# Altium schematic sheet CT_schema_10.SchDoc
size 318 x 188 mm
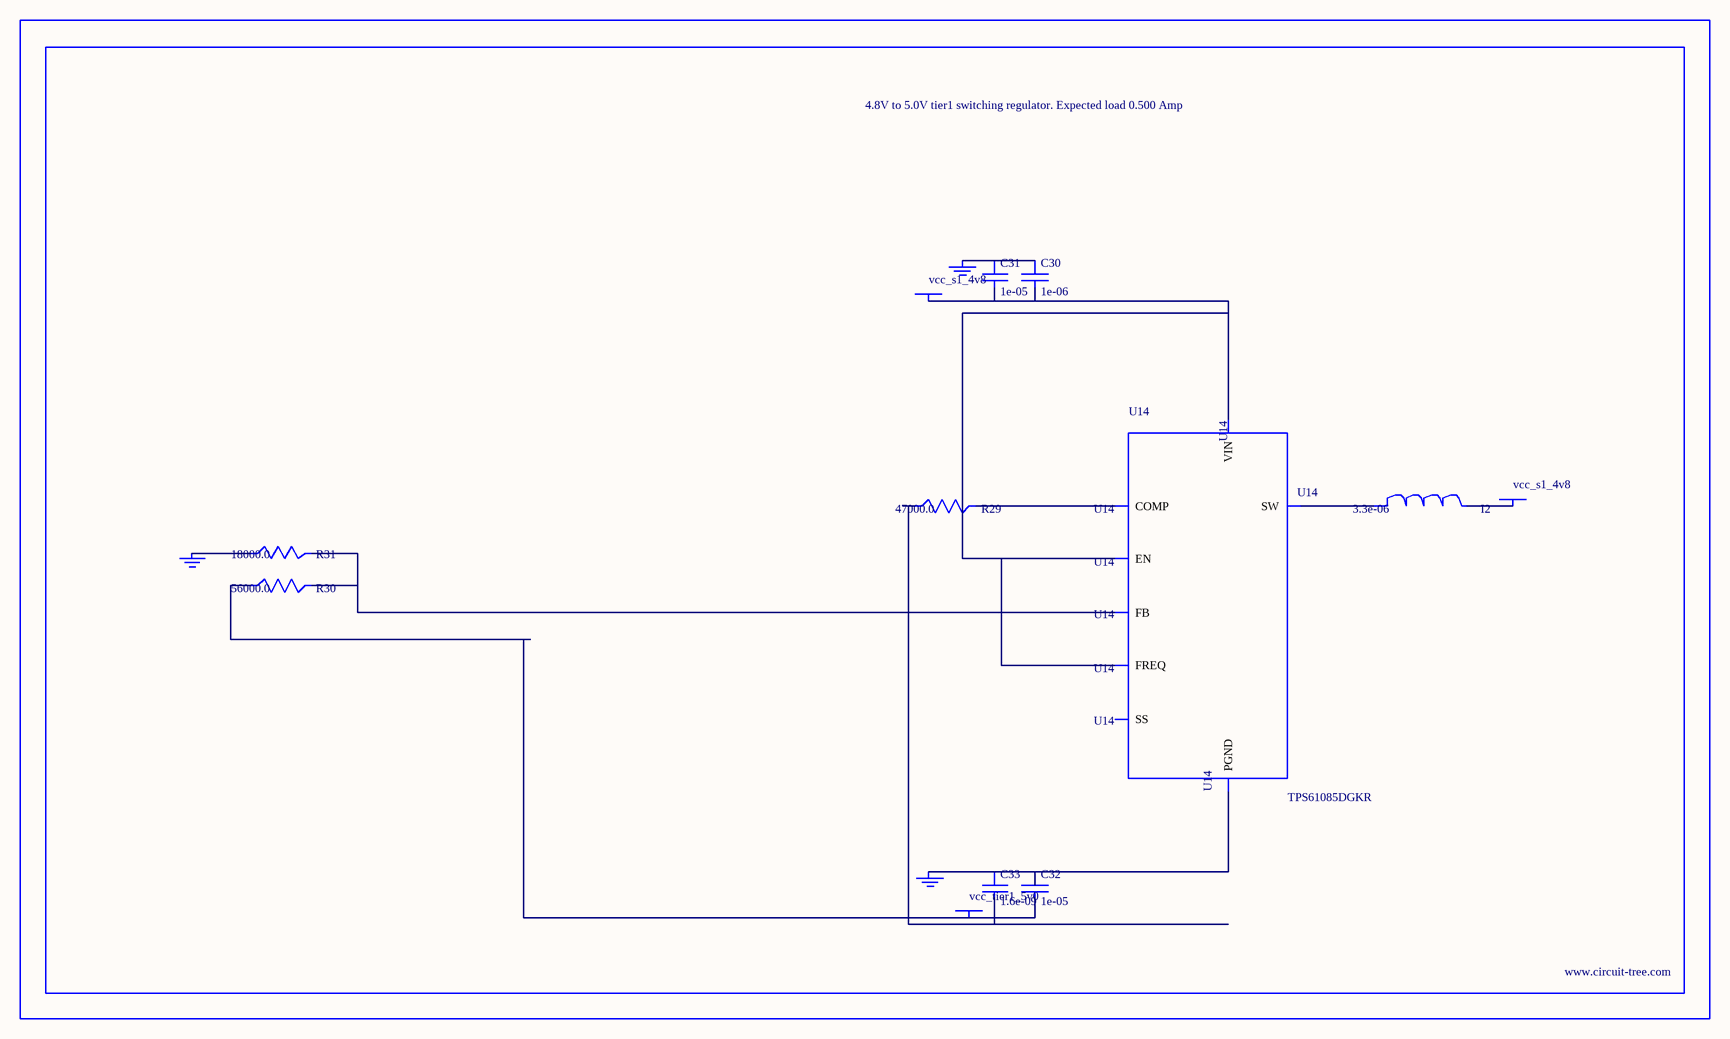
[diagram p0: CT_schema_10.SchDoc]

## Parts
BORDER9  (no value)
C30  1e-06  [C0603]
C31  1e-05  [C0805]
C32  1e-05  [C0805]
C33  1.6e-09  [C0603]
GND_INSTANCE_9_0  (no value)
GND_INSTANCE_9_1  (no value)
GND_INSTANCE_9_2  (no value)
I2  3.3e-06  [L0806]
POWER_INSTANCE_9_0  vcc_tier1_5v0
POWER_INSTANCE_9_1  vcc_s1_4v8
POWER_INSTANCE_9_2  vcc_s1_4v8
R29  47000.0  [R0603]
R30  56000.0  [R0603]
R31  18000.0  [R0603]
U14  TPS61085DGKR  [MSOP-8]

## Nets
NetC30_1: C30.1 C31.1 GND_INSTANCE_9_2.0(GND)
NetC30_2: C30.2 C31.2 POWER_INSTANCE_9_2.0(PWR) U14.3(EN) U14.6(VIN) U14.7(FREQ)
NetC32_1: C32.1 C33.1 GND_INSTANCE_9_1.0(GND) U14.4(PGND)
NetC32_2: C32.2 POWER_INSTANCE_9_0.0(PWR) R30.1
NetC33_2: C33.2 R29.1
NetGND_INSTANCE_9_0_0: GND_INSTANCE_9_0.0(GND) R31.1
NetI2_1: I2.1 U14.5(SW)
NetI2_2: I2.2 POWER_INSTANCE_9_1.0(PWR)
NetR29_2: R29.2 U14.1(COMP)
NetR30_2: R30.2 R31.2 U14.2(FB)

Not connected (* = marked no-connect by the designer): U14 8(SS)

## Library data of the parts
BORDER9 = BORDER_PAGE9
C30 = C0603C105K3RACTU
C31 C32 = C0805C106K8RACTU
C33 = 06035C162JAT2A
GND_INSTANCE_9_0-GND_INSTANCE_9_2 = GND
I2 = L0806C3R3MDWIT
POWER_INSTANCE_9_0-POWER_INSTANCE_9_2 = PWR
R29 = RC0603JR-0747KL
R30 = RC0603JR-0756KL
R31 = RC0603JR-0718KL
